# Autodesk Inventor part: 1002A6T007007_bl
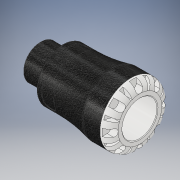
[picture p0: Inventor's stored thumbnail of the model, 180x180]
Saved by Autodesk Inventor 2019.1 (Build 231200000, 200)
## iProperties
Created: 2016-12
Part Number: 1002A6T007007_bl
Material: PVC-Piping
Description: PLASSON MALE ADAPTOR 3/4''IPS x 3/4''NPT SERIES 1
Document SubType Name: Modeling
Designer: KIM
Mass: 61.7504 g
Surface Area: 140.097 cm^2
Volume: 44.1074 cm^3
Density: 1.4 g/cm^3
Appearance: Black Cast
Author: KIM
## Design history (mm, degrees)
derived "1002A.ipt"
feature "Solid1::1002A.ipt" dims "ScaleForDerivedMember" = 10
tag "TaggingFeature1"
body "Solid1"
other parameters: "d0" = 75.946 [user parameter], "d1" = 20.16252 [user parameter], "d2" = 26.6 [user parameter], "d3" = 33.25 [user parameter], "d4" = 46.99 [user parameter], "d6" = 48.006 [user parameter], "d8" = 39.9415 [user parameter], "d13" = 5.496 [user parameter], "d14" = 5.496 [user parameter], "d15" = 0 [user parameter], "d17" = 360 deg [user parameter], "d19" = 8 deg [user parameter], "d20" = 0.532 [user parameter], "d21" = 0.532 [user parameter], "d22" = 8 deg [user parameter], "d24" = 0 [user parameter], "d26" = 360 deg [user parameter], "d32" = 0.925 [user parameter], "d33" = 4.699 [user parameter], "d34" = 26.441 [user parameter], "d35" = 3.325 [user parameter], "d38" = 17.018 [user parameter], "d39" = 0.79323 [user parameter], "d42" = 9.31 [user parameter], "d43" = 6.118 [user parameter], "d45" = 10.77216 [user parameter], "d46" = 0 [user parameter], "d59" = 360 deg [user parameter], "d61" = 7.9135 [user parameter], "d62" = 0.532 [user parameter], "d64" = 0 [user parameter], "d65" = 0.4699 [user parameter], "d_" = 26.6 [user parameter], "E_" = 46.99 [user parameter], "H_" = 75.946 [user parameter], "l_" = 48.006 [user parameter], "R_" = 26.441 [user parameter], "l_2" = 17.018 [user parameter], "d9" = 6.87 [user parameter], "d11" = 46.99 [user parameter], "d12" = 33.25 [user parameter]
